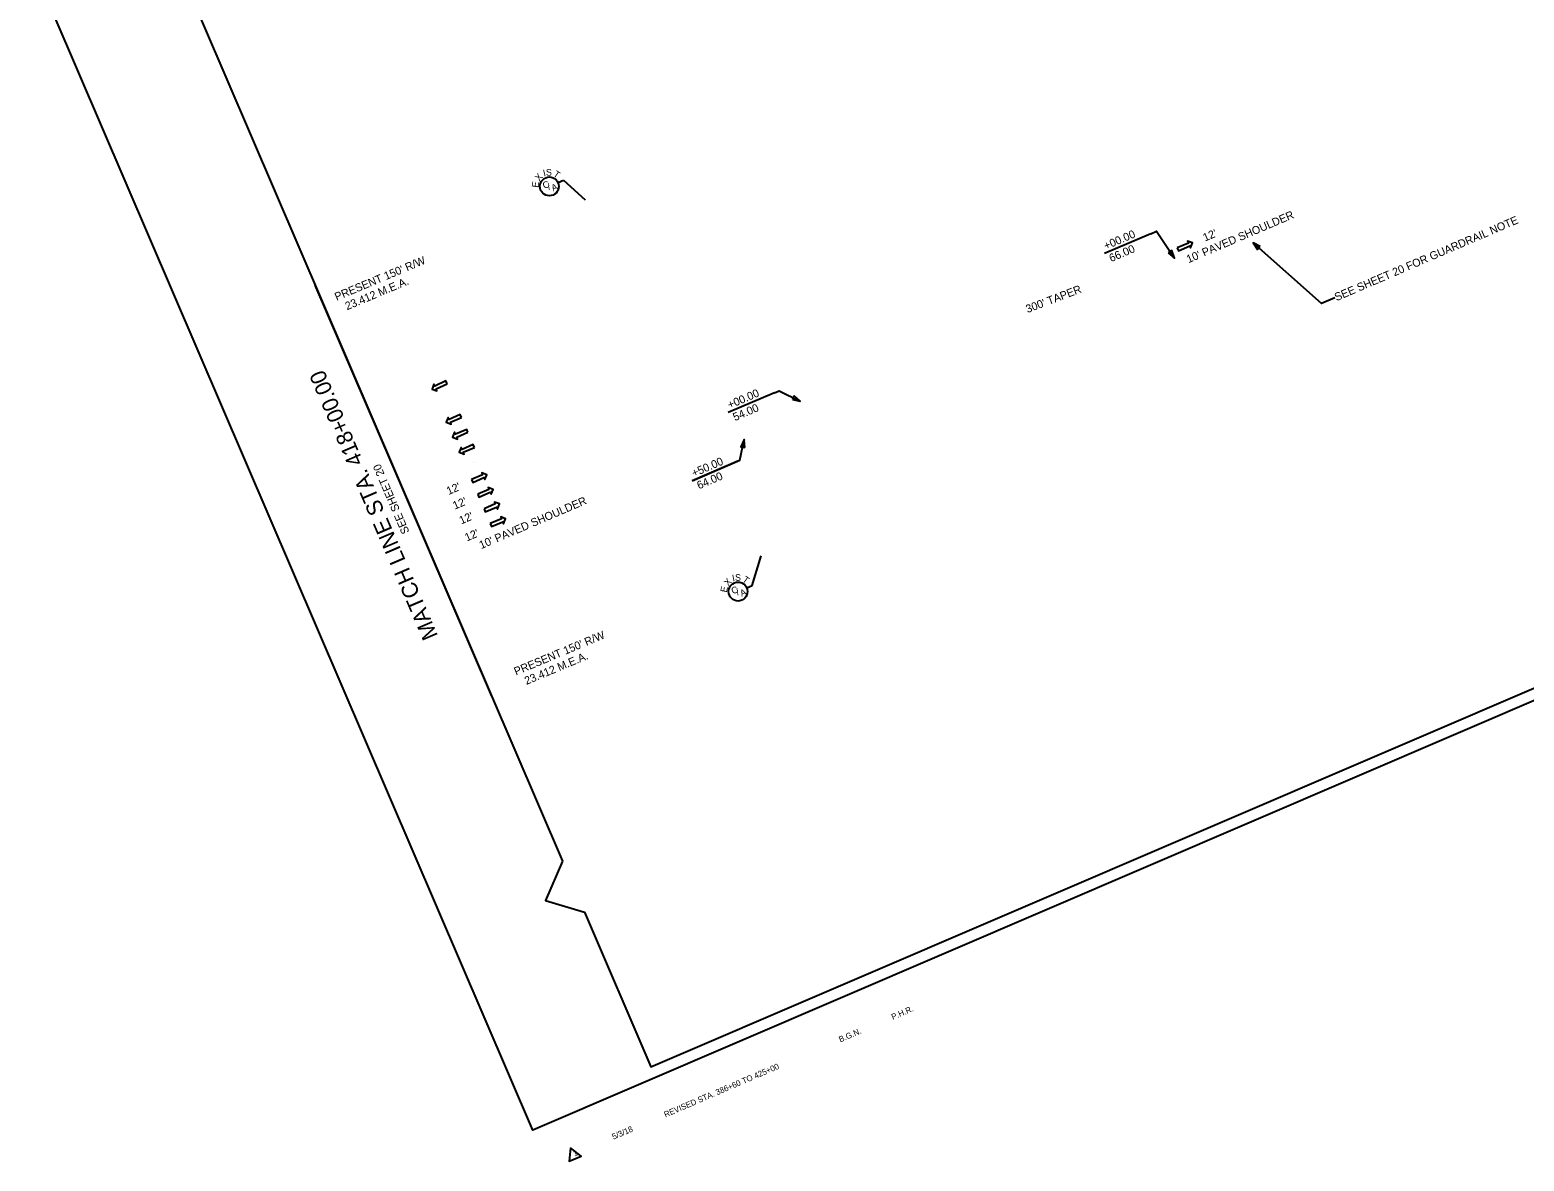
# Model space of a CAD drawing. Extents: x 1619612 to 1621672, y 1101722 to 1103419.
# Drawn here: x 1619612 to 1620732, y 1101722 to 1102571 of the extents above; entities that cross this region are included whole.
import ezdxf

# ---------------------------------------------------------------- set-up
doc = ezdxf.new("R2010")
doc.units = 0
for name, color, linetype in [('RD_EX_BldgApp', 7, 'Continuous'), ('RD_EX_Fence_Other', 7, 'Continuous'), ('RD_EX_H2O_WetLd', 7, 'Continuous'), ('RD_EX_Misc', 7, 'Continuous'), ('RD_EX_Misc_Golf_Teebox', 7, 'Continuous'), ('RD_EX_RailRoad', 7, 'Continuous'), ('RD_EX_VEG', 7, 'Continuous'), ('RD_HC_Data', 7, 'Continuous')]:
    doc.layers.add(name, color=color, linetype=linetype)

msp = doc.modelspace()

# ---------------------------------------------------------------- linework, layer by layer
at = {"layer": 'RD_EX_Fence_Other'}
msp.add_lwpolyline([(1619611.6, 1102624.3), (1621150.8, 1103284.9), (1621528, 1102405.9), (1619988.8, 1101745.3)], close=True, dxfattribs=at)
at = {"layer": 'RD_EX_H2O_WetLd'}
msp.add_lwpolyline([(1620590.2, 1102369.8), (1620580.1, 1102365.5), (1620528.8, 1102411)], dxfattribs=at)
msp.add_lwpolyline([(1620534.2, 1102408.3), (1620528.8, 1102411), (1620532.1, 1102406)], close=True, dxfattribs=at)
at = {"layer": 'RD_EX_Misc'}
for points in [[(1620471.9, 1102407.2), (1620472.9, 1102405), (1620481.3, 1102408.6), (1620482, 1102407.1), (1620483.4, 1102410.9), (1620479.7, 1102412.3), (1620480.4, 1102410.8)], [(1619924.4, 1102305.2), (1619923.4, 1102307.4), (1619915.1, 1102303.5), (1619914.4, 1102304.9), (1619913.1, 1102301.2), (1619916.8, 1102299.8), (1619916.1, 1102301.3)], [(1619935.3, 1102279.9), (1619934.3, 1102282.1), (1619925.9, 1102278.5), (1619925.3, 1102280), (1619923.8, 1102276.3), (1619927.5, 1102274.8), (1619926.9, 1102276.3)], [(1619940, 1102268.8), (1619939.1, 1102271), (1619930.7, 1102267.4), (1619930, 1102268.9), (1619928.5, 1102265.2), (1619932.3, 1102263.7), (1619931.6, 1102265.2)], [(1619944.9, 1102257.4), (1619944, 1102259.6), (1619935.6, 1102256), (1619934.9, 1102257.5), (1619933.4, 1102253.8), (1619937.1, 1102252.3), (1619936.5, 1102253.8)], [(1619942.6, 1102233.4), (1619943.6, 1102231.2), (1619952, 1102234.8), (1619952.6, 1102233.3), (1619954.1, 1102237), (1619950.4, 1102238.5), (1619951, 1102237)], [(1619947.4, 1102222.4), (1619948.3, 1102220.2), (1619956.7, 1102223.8), (1619957.4, 1102222.3), (1619958.9, 1102226), (1619955.1, 1102227.5), (1619955.8, 1102226)], [(1619952.1, 1102211.3), (1619953, 1102209.1), (1619961.5, 1102212.7), (1619962.1, 1102211.2), (1619963.6, 1102215), (1619959.9, 1102216.4), (1619960.5, 1102215)], [(1619956.8, 1102200.3), (1619957.8, 1102198.1), (1619966.2, 1102201.7), (1619966.8, 1102200.2), (1619968.3, 1102203.9), (1619964.6, 1102205.4), (1619965.2, 1102203.9)]]:
    msp.add_lwpolyline(points, close=True, dxfattribs=at)
at = {"layer": 'RD_EX_Misc_Golf_Teebox'}
for p, q in [((1620452.1, 1102417.8), (1620417.4, 1102402.9)), ((1620170, 1102298.5), (1620135.3, 1102283.6)), ((1619944.4, 1102245.9), (1619944.4, 1102245.9)), ((1620143, 1102247.4), (1620108.3, 1102232.5))]:
    msp.add_line(p, q, dxfattribs=at)
for points in [[(1620452.1, 1102417.8), (1620456.3, 1102419.6), (1620469.8, 1102399.5)], [(1620170, 1102298.5), (1620173.4, 1102300), (1620189.3, 1102292.2)], [(1620108.3, 1102232.5), (1620143.9, 1102247.8), (1620147.3, 1102263.3)]]:
    msp.add_lwpolyline(points, dxfattribs=at)
for points in [[(1620465.2, 1102403.5), (1620469.8, 1102399.5), (1620467.8, 1102405.2)], [(1620183.5, 1102293.4), (1620189.3, 1102292.2), (1620184.8, 1102296.2)], [(1620147.6, 1102257.3), (1620147.3, 1102263.3), (1620144.6, 1102258)], [(1620017, 1101731.9), (1620016, 1101722), (1620024.9, 1101725.8)]]:
    msp.add_lwpolyline(points, close=True, dxfattribs=at)
at = {"layer": 'RD_EX_RailRoad'}
msp.add_lwpolyline([(1620011, 1101947.1), (1619998.1, 1101917.6), (1620027.5, 1101908.7), (1620077.3, 1101792.6), (1621455.7, 1102384.2), (1621344.3, 1102622.5), (1621323.6, 1102755.5), (1621298.9, 1102749.7), (1621097, 1103220), (1620951.5, 1103157.1), (1620938.4, 1103188.8), (1619705.3, 1102659.5)], close=True, dxfattribs=at)
msp.add_lwpolyline([(1620011, 1101947.1), (1619998.1, 1101917.6), (1620027.5, 1101908.7), (1620077.3, 1101792.6), (1621455.7, 1102384.2), (1621344.3, 1102622.5), (1621323.6, 1102755.5), (1621298.9, 1102749.7), (1621097, 1103220), (1620951.5, 1103157.1), (1620938.4, 1103188.8), (1619705.3, 1102659.5)], close=True, dxfattribs=at)
at = {"layer": 'RD_EX_VEG'}
msp.add_lwpolyline([(1619957.9, 1102070.9), (1619892.4, 1102223.5), (1619825.6, 1102379.1)], dxfattribs=at)
at = {"layer": 'RD_HC_Data'}
for p, q in [((1620007.6, 1102456.1), (1620011.8, 1102457.9)), ((1620011.8, 1102457.9), (1620027.9, 1102443.1)), ((1620153.3, 1102153.9), (1620160, 1102176.2)), ((1620149.1, 1102152.1), (1620153.3, 1102153.9))]:
    msp.add_line(p, q, dxfattribs=at)
for centre in [(1620001.1, 1102453.3), (1620142.6, 1102149.3)]:
    msp.add_circle(centre, 7.08, dxfattribs=at)

# ---------------------------------------------------------------- texts
at = {"layer": 'RD_EX_BldgApp'}
for s, p in [("PRESENT 150' R/W ", (1619841.6, 1102367.4)), ('  23.412 M.E.A.', (1619845.3, 1102358.6)), ("PRESENT 150' R/W ", (1619976.1, 1102086.3)), ('  23.412 M.E.A.', (1619979.8, 1102077.5))]:
    msp.add_text(s, height=6, rotation=22.7764, dxfattribs=at).set_placement(p)
at = {"layer": 'RD_EX_H2O_WetLd'}
msp.add_text('SEE SHEET 20 FOR GUARDRAIL NOTE', height=6, rotation=23.2284, dxfattribs=at).set_placement((1620591.4, 1102367.1))
at = {"layer": 'RD_EX_Misc_Golf_Teebox'}
for s, height, rotation, p in [("10' PAVED SHOULDER", 6, 23.2363, (1620480.4, 1102395.6)), ('+00.00', 6, 23.2284, (1620418.4, 1102405.6)), ("12'", 6, 23.2346, (1620492.7, 1102411.8)), ('66.00', 6, 23.2284, (1620422.4, 1102396.4)), ("300' TAPER", 6, 20.9377, (1620359.7, 1102358.2)), ('+00.00', 6, 23.2284, (1620136.3, 1102286.3)), ('54.00', 6, 23.2284, (1620140.3, 1102277.1)), ('+50.00', 6, 23.2284, (1620109.4, 1102235.1)), ("12'", 6, 23.2346, (1619925.5, 1102221.7)), ('64.00', 6, 23.2284, (1620113.3, 1102225.9)), ("12'", 6, 23.2346, (1619930.2, 1102210.7)), ("10' PAVED SHOULDER", 6, 23.2363, (1619950, 1102181.1)), ("12'", 6, 23.2346, (1619935, 1102199.6)), ("12'", 6, 23.2346, (1619939.2, 1102186.8)), ('P.H.R.', 4.4, 23.2284, (1620258.7, 1101827.9)), ('B.G.N.', 4.4, 23.2284, (1620219.3, 1101811)), ('REVISED STA. 386+60 TO 425+00', 4.4, 23.2284, (1620088.2, 1101754.7)), ('5/3/18', 4.4, 23.2284, (1620049.2, 1101738)), ('1', 4.4, 23.2284, (1620019.9, 1101725.4))]:
    msp.add_text(s, height=height, rotation=rotation, dxfattribs=at).set_placement(p)
at = {"layer": 'RD_EX_VEG'}
for s, height, p in [('MATCH LINE STA. 418+00.00', 12, (1619917.8, 1102116.1)), ('SEE SHEET 20', 6, (1619896.3, 1102194))]:
    msp.add_text(s, height=height, rotation=113.2284, dxfattribs=at).set_placement(p)
at = {"layer": 'RD_HC_Data'}
for s, rotation, p in [('I', 13.1604, (1619997, 1102460.7)), ('S', 1.4399, (1619998.6, 1102461.3)), ('T', 326.2784, (1620003.6, 1102461.4)), ('E', 81.809, (1619992.8, 1102452.1)), ('X', 48.3219, (1619993.5, 1102456.9)), ('C', 23.2251, (1619997.3, 1102451.3)), ('/', 23.2251, (1620000.8, 1102450.5)), ('A', 23.2251, (1620003.8, 1102449.4)), ('I', 11.2082, (1620138.7, 1102156.8)), ('S', 359.4878, (1620140.3, 1102157.4)), ('E', 79.8568, (1620134.2, 1102148.4)), ('X', 46.3697, (1620135.1, 1102153.2)), ('C', 23.2251, (1620138.8, 1102147.2)), ('/', 23.2251, (1620142.3, 1102146.5)), ('A', 23.2251, (1620145.3, 1102145.4)), ('T', 324.3263, (1620145.4, 1102157.3))]:
    msp.add_text(s, height=5, rotation=rotation, dxfattribs=at).set_placement(p)

doc.saveas('drawing.dxf')
